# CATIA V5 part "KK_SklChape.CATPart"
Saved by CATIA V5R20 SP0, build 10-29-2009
Part number: skl chape
Bounding box of the stored display mesh (mm): x 900 to 900, y -100 to 100, z -350 to -350
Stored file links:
  G:\Khaled_CFAO_2011\ST2M\ST2M_GR2\tcorbin\Khaled\CAD_ThinkMOTION\KK_SklChape.CATPart
  F:\Thinkmotionperso\assemblage robot\ass_skl_robot.CATProduct
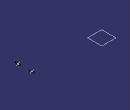
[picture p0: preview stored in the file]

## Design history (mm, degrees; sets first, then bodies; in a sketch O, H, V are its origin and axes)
External parameters (linked from other documents)
  `External.epaisseur soc_espacechape` = 160 mm
  `External.epaisseur avbrasbras` = 50 mm
  `External.longueur moteur` = 190 mm
  `External.hauteur chape` = 200 mm
  `External.hauteur soc` = 100 mm
Set1
  Plane1: type Offset, RefPlane xy-plane, Offset 500 {= `External.epaisseur avbrasbras` +`External.epaisseur avbrasbras` +`External.longueur moteur` +(`External.hauteur soc` /2)+10mm+`External.hauteur chape` -50mm}, reversed
  Point1: (900, 80 {= `External.epaisseur soc_espacechape` /2}, -350)
  Point2: (900, -80 {= -`External.epaisseur soc_espacechape` /2}, -350)
  Line1: type PtDir, RefPoint Point2, Direction zx-plane, Start -20, End 20
  Line2: type PtDir, RefPoint Point1, Direction zx-plane, Start -20, End 20
Body1 (main body)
